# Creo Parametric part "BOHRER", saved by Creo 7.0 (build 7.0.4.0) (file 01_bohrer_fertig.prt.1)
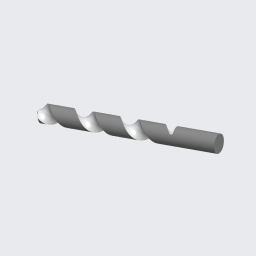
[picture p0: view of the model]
Units: millimeter Kilogram Sec (mmKs); MM, KILOGRAM, SECS
Materials in the file: S235JRG2

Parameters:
  PTC_MATERIAL_NAME = "S235JRG2"
  BENENNUNG = "XXX"
  DATUM = "XX.XX.XX"
  ERSTELLER = "ARINDA"
  TEILETYP = "Fertigungsteil"
  SELECT_EN_NAME = "S235JRG2"
  SELECT_DIN_NAME = "RSt37-2"
  SELECT_DIN_NUMBER = "1.0038"
  SELECT_ASTM_NAME = "A 283 M Grade 2"
  MATERIAL_GROUP = "ME_ST_Baustahl"
  STANDARD_EN_DELIVERYSPEC = "DIN EN 10025"
  STANDARD_DIN_DELIVERYSPEC = "DIN 17100"

Other parameters: MASSE

Created from: ARINDA-STARTTEIL.PRT

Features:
  1. coordinate system "CS0"
  2. datum plane "DTM1", "T_RECHTS_Y-Z"
  3. datum plane "DTM2", "T_OBEN_X-Z"
  4. datum plane "DTM3", "T_VORNE_X-Y"
  5. datum axis "T_X-ACHSE"
  6. datum axis "A_1"
  7. datum axis "A_2"
  8. revolve "Drehen 1"
  9. cut "Spiralförmiges Volumen-Zug-Ke 1"

Other named items: T_BASIC, T_Y-ACHSE, T_Z-ACHSE

Layers: 00_STD-ACHSEN, 00_STD-EBENEN, 00_STD-KOORDSYS, VOLUMENGEOMETRIE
